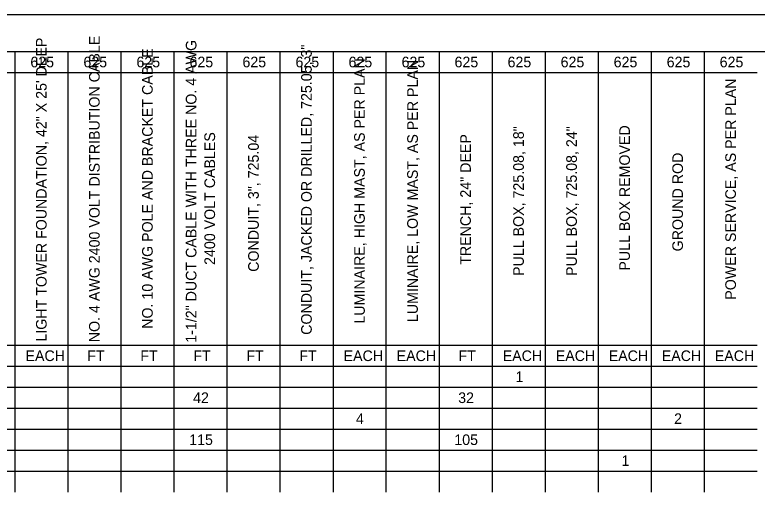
# Model space of a CAD drawing. Extents: x 0 to 34, y 0 to 22.
# Drawn here: x 16.82 to 26.95, y 15.49 to 22 of the extents above; entities that cross this region are included whole.
import ezdxf

# ---------------------------------------------------------------- set-up
doc = ezdxf.new("R2010")
doc.units = 0
for name, color, linetype in [('Default', 7, 'Continuous'), ('SH_Border', 7, 'Continuous'), ('SH_Cut_Line', 7, 'Continuous')]:
    doc.layers.add(name, color=color, linetype=linetype)

msp = doc.modelspace()

# ---------------------------------------------------------------- linework, layer by layer
at = {"layer": 'Default'}
for p, q in [((15.374, 21.5), (16.822, 21.5)), ((16.822, 21.5), (23.336, 21.5)), ((16.822, 21.5), (16.822, 21.214)), ((17.546, 21.5), (17.546, 21.214)), ((18.27, 21.5), (18.27, 21.214)), ((18.993, 21.5), (18.993, 21.214)), ((19.717, 21.5), (19.717, 21.214)), ((20.441, 21.5), (20.441, 21.214)), ((21.165, 21.5), (21.165, 21.214)), ((21.888, 21.5), (21.888, 21.214)), ((22.612, 21.5), (22.612, 21.214)), ((23.336, 21.5), (24.06, 21.5)), ((23.336, 21.5), (23.336, 21.214)), ((24.06, 21.5), (26.231, 21.5)), ((24.06, 21.5), (24.06, 21.214)), ((24.783, 21.5), (24.783, 21.214)), ((25.507, 21.5), (25.507, 21.214)), ((26.231, 21.5), (26.955, 21.5)), ((26.231, 21.5), (26.231, 21.214)), ((15.374, 21.214), (16.822, 21.214)), ((16.822, 21.214), (23.336, 21.214)), ((16.822, 21.214), (16.822, 20.927)), ((17.546, 21.214), (17.546, 20.927)), ((18.27, 21.214), (18.27, 20.927)), ((18.993, 21.214), (18.993, 20.927)), ((19.717, 21.214), (19.717, 20.927)), ((20.441, 21.214), (20.441, 20.927)), ((21.165, 21.214), (21.165, 20.927)), ((21.888, 21.214), (21.888, 20.927)), ((22.612, 21.214), (22.612, 20.927)), ((23.336, 21.214), (24.06, 21.214)), ((23.336, 21.214), (23.336, 20.927)), ((24.06, 21.214), (26.231, 21.214)), ((24.06, 21.214), (24.06, 20.927)), ((24.783, 21.214), (24.783, 20.927)), ((25.507, 21.214), (25.507, 20.927)), ((26.231, 21.214), (26.955, 21.214)), ((26.231, 21.214), (26.231, 20.927)), ((16.822, 20.927), (16.822, 20.641)), ((17.546, 20.927), (17.546, 20.641)), ((18.27, 20.927), (18.27, 20.641)), ((18.993, 20.927), (18.993, 20.641)), ((19.717, 20.927), (19.717, 20.641)), ((20.441, 20.927), (20.441, 20.641)), ((21.165, 20.927), (21.165, 20.641)), ((21.888, 20.927), (21.888, 20.641)), ((22.612, 20.927), (22.612, 20.641)), ((23.336, 20.927), (23.336, 20.641)), ((24.06, 20.927), (24.06, 20.641)), ((24.783, 20.927), (24.783, 20.641)), ((25.507, 20.927), (25.507, 20.641)), ((26.231, 20.927), (26.231, 20.641)), ((16.822, 20.641), (16.822, 20.354)), ((17.546, 20.641), (17.546, 20.354)), ((18.27, 20.641), (18.27, 20.354)), ((18.993, 20.641), (18.993, 20.354)), ((19.717, 20.641), (19.717, 20.354)), ((20.441, 20.641), (20.441, 20.354)), ((21.165, 20.641), (21.165, 20.354)), ((21.888, 20.641), (21.888, 20.354)), ((22.612, 20.641), (22.612, 20.354)), ((23.336, 20.641), (23.336, 20.354)), ((24.06, 20.641), (24.06, 20.354)), ((24.783, 20.641), (24.783, 20.354)), ((25.507, 20.641), (25.507, 20.354)), ((26.231, 20.641), (26.231, 20.354)), ((16.822, 20.354), (16.822, 20.068)), ((17.546, 20.354), (17.546, 20.068)), ((18.27, 20.354), (18.27, 20.068)), ((18.993, 20.354), (18.993, 20.068)), ((19.717, 20.354), (19.717, 20.068)), ((20.441, 20.354), (20.441, 20.068)), ((21.165, 20.354), (21.165, 20.068)), ((21.888, 20.354), (21.888, 20.068)), ((22.612, 20.354), (22.612, 20.068)), ((23.336, 20.354), (23.336, 20.068)), ((24.06, 20.354), (24.06, 20.068)), ((24.783, 20.354), (24.783, 20.068)), ((25.507, 20.354), (25.507, 20.068)), ((26.231, 20.354), (26.231, 20.068)), ((16.822, 20.068), (16.822, 19.782)), ((17.546, 20.068), (17.546, 19.782)), ((18.27, 20.068), (18.27, 19.782)), ((18.993, 20.068), (18.993, 19.782)), ((19.717, 20.068), (19.717, 19.782)), ((20.441, 20.068), (20.441, 19.782)), ((21.165, 20.068), (21.165, 19.782)), ((21.888, 20.068), (21.888, 19.782)), ((22.612, 20.068), (22.612, 19.782)), ((23.336, 20.068), (23.336, 19.782)), ((24.06, 20.068), (24.06, 19.782)), ((24.783, 20.068), (24.783, 19.782)), ((25.507, 20.068), (25.507, 19.782)), ((26.231, 20.068), (26.231, 19.782)), ((16.822, 19.782), (16.822, 19.495)), ((17.546, 19.782), (17.546, 19.495)), ((18.27, 19.782), (18.27, 19.495)), ((18.993, 19.782), (18.993, 19.495)), ((19.717, 19.782), (19.717, 19.495)), ((20.441, 19.782), (20.441, 19.495)), ((21.165, 19.782), (21.165, 19.495)), ((21.888, 19.782), (21.888, 19.495)), ((22.612, 19.782), (22.612, 19.495)), ((23.336, 19.782), (23.336, 19.495)), ((24.06, 19.782), (24.06, 19.495)), ((24.783, 19.782), (24.783, 19.495)), ((25.507, 19.782), (25.507, 19.495)), ((26.231, 19.782), (26.231, 19.495)), ((16.822, 19.495), (16.822, 19.209)), ((17.546, 19.495), (17.546, 19.209)), ((18.27, 19.495), (18.27, 19.209)), ((18.993, 19.495), (18.993, 19.209)), ((19.717, 19.495), (19.717, 19.209)), ((20.441, 19.495), (20.441, 19.209)), ((21.165, 19.495), (21.165, 19.209)), ((21.888, 19.495), (21.888, 19.209)), ((22.612, 19.495), (22.612, 19.209)), ((23.336, 19.495), (23.336, 19.209)), ((24.06, 19.495), (24.06, 19.209)), ((24.783, 19.495), (24.783, 19.209)), ((25.507, 19.495), (25.507, 19.209)), ((26.231, 19.495), (26.231, 19.209)), ((16.822, 19.209), (16.822, 18.922)), ((17.546, 19.209), (17.546, 18.922)), ((18.27, 19.209), (18.27, 18.922)), ((18.993, 19.209), (18.993, 18.922)), ((19.717, 19.209), (19.717, 18.922)), ((20.441, 19.209), (20.441, 18.922)), ((21.165, 19.209), (21.165, 18.922)), ((21.888, 19.209), (21.888, 18.922)), ((22.612, 19.209), (22.612, 18.922)), ((23.336, 19.209), (23.336, 18.922)), ((24.06, 19.209), (24.06, 18.922)), ((24.783, 19.209), (24.783, 18.922)), ((25.507, 19.209), (25.507, 18.922)), ((26.231, 19.209), (26.231, 18.922)), ((16.822, 18.922), (16.822, 18.636)), ((17.546, 18.922), (17.546, 18.636)), ((18.27, 18.922), (18.27, 18.636)), ((18.993, 18.922), (18.993, 18.636)), ((19.717, 18.922), (19.717, 18.636)), ((20.441, 18.922), (20.441, 18.636)), ((21.165, 18.922), (21.165, 18.636)), ((21.888, 18.922), (21.888, 18.636)), ((22.612, 18.922), (22.612, 18.636)), ((23.336, 18.922), (23.336, 18.636)), ((24.06, 18.922), (24.06, 18.636)), ((24.783, 18.922), (24.783, 18.636)), ((25.507, 18.922), (25.507, 18.636)), ((26.231, 18.922), (26.231, 18.636)), ((16.822, 18.636), (16.822, 18.35)), ((17.546, 18.636), (17.546, 18.35)), ((18.27, 18.636), (18.27, 18.35)), ((18.993, 18.636), (18.993, 18.35)), ((19.717, 18.636), (19.717, 18.35)), ((20.441, 18.636), (20.441, 18.35)), ((21.165, 18.636), (21.165, 18.35)), ((21.888, 18.636), (21.888, 18.35)), ((22.612, 18.636), (22.612, 18.35)), ((23.336, 18.636), (23.336, 18.35)), ((24.06, 18.636), (24.06, 18.35)), ((24.783, 18.636), (24.783, 18.35)), ((25.507, 18.636), (25.507, 18.35)), ((26.231, 18.636), (26.231, 18.35)), ((16.822, 18.35), (16.822, 18.063)), ((17.546, 18.35), (17.546, 18.063)), ((18.27, 18.35), (18.27, 18.063)), ((18.993, 18.35), (18.993, 18.063)), ((19.717, 18.35), (19.717, 18.063)), ((20.441, 18.35), (20.441, 18.063)), ((21.165, 18.35), (21.165, 18.063)), ((21.888, 18.35), (21.888, 18.063)), ((22.612, 18.35), (22.612, 18.063)), ((23.336, 18.35), (23.336, 18.063)), ((24.06, 18.35), (24.06, 18.063)), ((24.783, 18.35), (24.783, 18.063)), ((25.507, 18.35), (25.507, 18.063)), ((26.231, 18.35), (26.231, 18.063)), ((16.822, 18.063), (16.822, 17.777)), ((17.546, 18.063), (17.546, 17.777)), ((18.27, 18.063), (18.27, 17.777)), ((18.993, 18.063), (18.993, 17.777)), ((19.717, 18.063), (19.717, 17.777)), ((20.441, 18.063), (20.441, 17.777)), ((21.165, 18.063), (21.165, 17.777)), ((21.888, 18.063), (21.888, 17.777)), ((22.612, 18.063), (22.612, 17.777)), ((23.336, 18.063), (23.336, 17.777)), ((24.06, 18.063), (24.06, 17.777)), ((24.783, 18.063), (24.783, 17.777)), ((25.507, 18.063), (25.507, 17.777)), ((26.231, 18.063), (26.231, 17.777)), ((16.822, 17.777), (16.822, 17.49)), ((17.546, 17.777), (17.546, 17.49)), ((18.27, 17.777), (18.27, 17.49)), ((18.993, 17.777), (18.993, 17.49)), ((19.717, 17.777), (19.717, 17.49)), ((20.441, 17.777), (20.441, 17.49)), ((21.165, 17.777), (21.165, 17.49)), ((21.888, 17.777), (21.888, 17.49)), ((22.612, 17.777), (22.612, 17.49)), ((23.336, 17.777), (23.336, 17.49)), ((24.06, 17.777), (24.06, 17.49)), ((24.783, 17.777), (24.783, 17.49)), ((25.507, 17.777), (25.507, 17.49)), ((26.231, 17.777), (26.231, 17.49)), ((15.374, 17.49), (16.822, 17.49)), ((16.822, 17.49), (23.336, 17.49)), ((16.822, 17.49), (16.822, 17.204)), ((17.546, 17.49), (17.546, 17.204)), ((18.27, 17.49), (18.27, 17.204)), ((18.993, 17.49), (18.993, 17.204)), ((19.717, 17.49), (19.717, 17.204)), ((20.441, 17.49), (20.441, 17.204)), ((21.165, 17.49), (21.165, 17.204)), ((21.888, 17.49), (21.888, 17.204)), ((22.612, 17.49), (22.612, 17.204)), ((23.336, 17.49), (24.06, 17.49)), ((23.336, 17.49), (23.336, 17.204)), ((24.06, 17.49), (26.231, 17.49)), ((24.06, 17.49), (24.06, 17.204)), ((24.783, 17.49), (24.783, 17.204)), ((25.507, 17.49), (25.507, 17.204)), ((26.231, 17.49), (26.955, 17.49)), ((26.231, 17.49), (26.231, 17.204)), ((15.374, 17.204), (16.822, 17.204)), ((16.822, 17.204), (23.336, 17.204)), ((16.822, 17.204), (16.822, 16.918)), ((17.546, 17.204), (17.546, 16.918)), ((18.27, 17.204), (18.27, 16.918)), ((18.993, 17.204), (18.993, 16.918)), ((19.717, 17.204), (19.717, 16.918)), ((20.441, 17.204), (20.441, 16.918)), ((21.165, 17.204), (21.165, 16.918)), ((21.888, 17.204), (21.888, 16.918)), ((22.612, 17.204), (22.612, 16.918)), ((23.336, 17.204), (24.06, 17.204)), ((23.336, 17.204), (23.336, 16.918)), ((24.06, 17.204), (26.231, 17.204)), ((24.06, 17.204), (24.06, 16.918)), ((24.783, 17.204), (24.783, 16.918)), ((25.507, 17.204), (25.507, 16.918)), ((26.231, 17.204), (26.955, 17.204)), ((26.231, 17.204), (26.231, 16.918)), ((15.374, 16.918), (16.822, 16.918)), ((16.822, 16.918), (23.336, 16.918)), ((16.822, 16.918), (16.822, 16.631)), ((17.546, 16.918), (17.546, 16.631)), ((18.27, 16.918), (18.27, 16.631)), ((18.993, 16.918), (18.993, 16.631)), ((19.717, 16.918), (19.717, 16.631)), ((20.441, 16.918), (20.441, 16.631)), ((21.165, 16.918), (21.165, 16.631)), ((21.888, 16.918), (21.888, 16.631)), ((22.612, 16.918), (22.612, 16.631)), ((23.336, 16.918), (24.06, 16.918)), ((23.336, 16.918), (23.336, 16.631)), ((24.06, 16.918), (26.231, 16.918)), ((24.06, 16.918), (24.06, 16.631)), ((24.783, 16.918), (24.783, 16.631)), ((25.507, 16.918), (25.507, 16.631)), ((26.231, 16.918), (26.955, 16.918)), ((26.231, 16.918), (26.231, 16.631)), ((15.374, 16.631), (16.822, 16.631)), ((16.822, 16.631), (23.336, 16.631)), ((16.822, 16.631), (16.822, 16.345)), ((17.546, 16.631), (17.546, 16.345)), ((18.27, 16.631), (18.27, 16.345)), ((18.993, 16.631), (18.993, 16.345)), ((19.717, 16.631), (19.717, 16.345)), ((20.441, 16.631), (20.441, 16.345)), ((21.165, 16.631), (21.165, 16.345)), ((21.888, 16.631), (21.888, 16.345)), ((22.612, 16.631), (22.612, 16.345)), ((23.336, 16.631), (24.06, 16.631)), ((23.336, 16.631), (23.336, 16.345)), ((24.06, 16.631), (26.231, 16.631)), ((24.06, 16.631), (24.06, 16.345)), ((24.783, 16.631), (24.783, 16.345)), ((25.507, 16.631), (25.507, 16.345)), ((26.231, 16.631), (26.955, 16.631)), ((26.231, 16.631), (26.231, 16.345)), ((15.374, 16.345), (16.822, 16.345)), ((16.822, 16.345), (23.336, 16.345)), ((16.822, 16.345), (16.822, 16.058)), ((17.546, 16.345), (17.546, 16.058)), ((18.27, 16.345), (18.27, 16.058)), ((18.993, 16.345), (18.993, 16.058)), ((19.717, 16.345), (19.717, 16.058)), ((20.441, 16.345), (20.441, 16.058)), ((21.165, 16.345), (21.165, 16.058)), ((21.888, 16.345), (21.888, 16.058)), ((22.612, 16.345), (22.612, 16.058)), ((23.336, 16.345), (24.06, 16.345)), ((23.336, 16.345), (23.336, 16.058)), ((24.06, 16.345), (26.231, 16.345)), ((24.06, 16.345), (24.06, 16.058)), ((24.783, 16.345), (24.783, 16.058)), ((25.507, 16.345), (25.507, 16.058)), ((26.231, 16.345), (26.955, 16.345)), ((26.231, 16.345), (26.231, 16.058)), ((15.374, 16.058), (16.822, 16.058)), ((16.822, 16.058), (23.336, 16.058)), ((16.822, 16.058), (16.822, 15.772)), ((17.546, 16.058), (17.546, 15.772)), ((18.27, 16.058), (18.27, 15.772)), ((18.993, 16.058), (18.993, 15.772)), ((19.717, 16.058), (19.717, 15.772)), ((20.441, 16.058), (20.441, 15.772)), ((21.165, 16.058), (21.165, 15.772)), ((21.888, 16.058), (21.888, 15.772)), ((22.612, 16.058), (22.612, 15.772)), ((23.336, 16.058), (24.06, 16.058)), ((23.336, 16.058), (23.336, 15.772)), ((24.06, 16.058), (26.231, 16.058)), ((24.06, 16.058), (24.06, 15.772)), ((24.783, 16.058), (24.783, 15.772)), ((25.507, 16.058), (25.507, 15.772)), ((26.231, 16.058), (26.955, 16.058)), ((26.231, 16.058), (26.231, 15.772)), ((15.374, 15.772), (16.822, 15.772)), ((16.822, 15.772), (23.336, 15.772)), ((16.822, 15.772), (16.822, 15.486)), ((17.546, 15.772), (17.546, 15.486)), ((18.27, 15.772), (18.27, 15.486)), ((18.993, 15.772), (18.993, 15.486)), ((19.717, 15.772), (19.717, 15.486)), ((20.441, 15.772), (20.441, 15.486)), ((21.165, 15.772), (21.165, 15.486)), ((21.888, 15.772), (21.888, 15.486)), ((22.612, 15.772), (22.612, 15.486)), ((23.336, 15.772), (24.06, 15.772)), ((23.336, 15.772), (23.336, 15.486)), ((24.06, 15.772), (26.231, 15.772)), ((24.06, 15.772), (24.06, 15.486)), ((24.783, 15.772), (24.783, 15.486)), ((25.507, 15.772), (25.507, 15.486)), ((26.231, 15.772), (26.955, 15.772)), ((26.231, 15.772), (26.231, 15.486))]:
    msp.add_line(p, q, dxfattribs=at)
at = {"layer": 'SH_Border'}
msp.add_lwpolyline([(1.5, 21.5), (33.5, 21.5), (33.5, 0.5), (1.5, 0.5)], close=True, dxfattribs=at)
at = {"layer": 'SH_Cut_Line'}
msp.add_lwpolyline([(0, 0), (34, 0), (34, 22), (0, 22)], close=True, dxfattribs=at)

# ---------------------------------------------------------------- texts
at = {"layer": 'Default'}
for s, height, p in [('NO. 4 AWG 2400 VOLT DISTRIBUTION CABLE', 0.14509, (17.98, 17.532)), ('LIGHT TOWER FOUNDATION, 42" X 25\' DEEP', 0.14509, (17.256, 17.54)), ('1-1/2" DUCT CABLE WITH THREE NO. 4 AWG ', 0.14509, (19.301, 17.525)), ('CONDUIT, JACKED OR DRILLED, 725.05, 3"', 0.14509, (20.875, 17.633)), ('NO. 10 AWG POLE AND BRACKET CABLE', 0.14509, (18.704, 17.715)), ('LUMINAIRE, HIGH MAST, AS PER PLAN', 0.14509, (21.599, 17.786)), ('LUMINAIRE, LOW MAST, AS PER PLAN', 0.14509, (22.323, 17.806)), ('POWER SERVICE, AS PER PLAN', 0.14509, (26.665, 18.112)), ('PULL BOX, 725.08, 18"', 0.14509, (23.77, 18.437)), ('PULL BOX, 725.08, 24"', 0.14509, (24.494, 18.437)), ('PULL BOX REMOVED', 0.14509, (25.218, 18.509)), ('2400 VOLT CABLES', 0.14509, (19.555, 18.587)), ('CONDUIT, 3", 725.04', 0.14509, (20.152, 18.493)), ('TRENCH, 24" DEEP', 0.14509, (23.047, 18.589)), ('GROUND ROD', 0.1451, (25.942, 18.772))]:
    msp.add_text(s, height=height, rotation=90, dxfattribs=at).set_placement(p)
for s, height, p in [('625', 0.1449, (17.034, 21.284)), ('625', 0.1449, (17.758, 21.284)), ('625', 0.1449, (18.482, 21.284)), ('625', 0.1449, (19.206, 21.284)), ('625', 0.1449, (19.929, 21.284)), ('625', 0.1449, (20.653, 21.284)), ('625', 0.1449, (21.377, 21.284)), ('625', 0.1449, (22.101, 21.284)), ('625', 0.1449, (22.824, 21.284)), ('625', 0.1449, (23.548, 21.284)), ('625', 0.1449, (24.272, 21.284)), ('625', 0.1449, (24.996, 21.284)), ('625', 0.1449, (25.72, 21.284)), ('625', 0.1449, (26.443, 21.284)), ('EACH', 0.1449, (16.968, 17.275)), ('FT', 0.1449, (17.811, 17.275)), ('FT', 0.1449, (18.535, 17.275)), ('FT', 0.1449, (19.259, 17.275)), ('FT', 0.1449, (19.983, 17.275)), ('FT', 0.1449, (20.706, 17.275)), ('EACH', 0.1449, (21.31, 17.275)), ('EACH', 0.1449, (22.034, 17.275)), ('FT', 0.1449, (22.878, 17.275)), ('EACH', 0.1449, (23.482, 17.275)), ('EACH', 0.1449, (24.206, 17.275)), ('EACH', 0.1449, (24.929, 17.275)), ('EACH', 0.1449, (25.653, 17.275)), ('EACH', 0.1449, (26.377, 17.275)), ('1', 0.145, (23.656, 16.988)), ('42', 0.1449, (19.255, 16.702)), ('32', 0.1449, (22.874, 16.702)), ('4', 0.145, (21.479, 16.416)), ('2', 0.145, (25.821, 16.416)), ('115', 0.1449, (19.202, 16.129)), ('105', 0.1449, (22.821, 16.129)), ('1', 0.145, (25.103, 15.843))]:
    msp.add_text(s, height=height, dxfattribs=at).set_placement(p)

doc.saveas('drawing.dxf')
